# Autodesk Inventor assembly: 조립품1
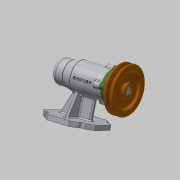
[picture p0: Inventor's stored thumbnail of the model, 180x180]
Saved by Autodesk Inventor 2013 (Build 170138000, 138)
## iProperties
Created: 2019-12
Part Number: 조립품1
Document SubType Name: Assembly
Designer: Administrator
Author: Administrator
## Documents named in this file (12)
- C:\Users\Administrator\Desktop\491204V1031\조립품1.iam
- C:\Users\Administrator\Desktop\491204V1031\부품1.ipt
- C:\Users\Administrator\Desktop\491204V1031\V벨트풀리.ipt
- C:\Users\Administrator\Desktop\491204V1031\멈춤나사 M3.ipt
- C:\Users\Administrator\Desktop\491204V1031\베어링 6004.ipt
- C:\Users\Administrator\Desktop\491204V1031\베어링 51202.ipt
- C:\Users\Administrator\Desktop\491204V1031\볼트 M4.ipt
- C:\Users\Administrator\Desktop\491204V1031\어댑터슬리브.ipt
- C:\Users\Administrator\Desktop\491204V1031\오일 실.ipt
- C:\Users\Administrator\Desktop\491204V1031\축.ipt
- C:\Users\Administrator\Desktop\491204V1031\커버.ipt
- C:\Users\Administrator\Desktop\491204V1031\키 5 x 5 x 16.ipt
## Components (1 placed, 1 different names)
1. V벨트풀리:1
